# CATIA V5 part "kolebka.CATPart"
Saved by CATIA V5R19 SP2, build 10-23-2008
Part number: kolebka
Bounding box of the stored display mesh (mm): x -580 to 1160, y -1200 to 1200, z -150 to 340
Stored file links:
  D:\Catia fórum\Modely - Otazky\Naklapeni_oprava\kolebka.CATPart
  C:\Program Files\Dassault Systemes\B19\intel_a\reffiles\standard\MetricThinPitch.txt
  C:\Program Files\Dassault Systemes\B19\intel_a\startup\materials\Catalog.CATMaterial
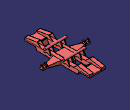
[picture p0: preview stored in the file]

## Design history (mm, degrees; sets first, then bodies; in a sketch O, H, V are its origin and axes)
WSupportSet1
Body1 (main body)
  Sketch1 on yz-plane, origin (0, 0, 0), H (0, 1, 0), V (0, 0, 1)
    construction line L1 (0, 482.4405) -> (0, -98.2488)
    point P1 (0, 482.4405)
    line L2 (0, 0) -> (-763.603, 0)
    point P3 (-763.603, 0)
    line L3 (-763.603, 0) -> (-800, 100)
    point P4 (-800, 100)
    line L4 (-800, 100) -> (-1200, 100)
    point P5 (-1200, 100)
    line L5 (-1200, 100) -> (-1200, 150)
    point P6 (-1200, 150)
    line L6 (-1200, 150) -> (0, 150)
    point P7 (0, 150)
    line L7 (0, 150) -> (0, 150)
    point P8 (0, 150)
    point P9 (0, 150)
    point P10 (763.603, 0)
    point P11 (800, 100)
    point P12 (1200, 100)
    point P13 (1200, 150)
    point P14 (0, 150)
    point P15 (0, 150)
    line L8 (763.603, 0) -> (800, 100)
    line L9 (800, 100) -> (1200, 100)
    line L10 (1200, 100) -> (1200, 150)
    line L11 (1200, 150) -> (0, 150)
    line L12 (0, 150) -> (0, 150)
    point P16 (0, 150)
    line L13 (0, 150) -> (0, 150)
    point P17 (0, 0)
    line L14 (0, 0) -> (763.603, 0)
    line L15 (-755.7735, 140) -> (-755.7735, 140)
    line L16 (755.7735, 140) -> (755.7735, 140)
    distance L5 L1 = 1200
    distance L4 L6 = 50
    distance L2 L4 = 100
    angle L2 L3 = 110
    distance P4 L5 = 400
    coincidence: P1 V, P9 L1, O P17, P9 P16, P7 P9
    vertical: L1 V, L5 V
    horizontal: L2 H, L4 H, L6 H
    symmetry: P3 P10 L1, P4 P11 L1, P5 P12 L1, P6 P13 L1, P7 P14 L1, P8 P15 L1, L3 L8 L1, L4 L9 L1, L5 L10 L1, L6 L11 L1, L7 L12 L1, P9 P16 L1, O P17 L1, L2 L14 L1
  Pad1: profile Sketch1, direction (1, 0, 0), length 140
  Shell1: IntOffset 10, Face face of Pad1 from Sketch1.L11, ExtOffset 0
  Sketch2 on face of Shell1, origin (0, -1190, 0), H (-1, 0, 0), V (0, 0, 1)
    line L1 (-130, 150) -> (-10, 150)
    line L2 (-10, 150) -> (-10, 140)
    line L3 (-10, 140) -> (-130, 140)
    line L4 (-130, 140) -> (-130, 150)
    reference projected line E1 (-130, 150) -> (-130, 110) from edge [face of Shell1 | face of Shell1]
    reference projected line E2 (-10, 150) -> (-190, 150) from edge [face of Pad1 from Sketch1.L6 | face of Shell1]
    reference projected line E3 (-10, 150) -> (-10, 110) from edge [face of Shell1 | face of Shell1]
    distance L3 L1 = 10
    horizontal: L1 H, L3 H
    vertical: L2 V, L4 V
    coincidence: E1 L4, L1 E2, E3 L2
  Pad2: profile Sketch2, direction (0, 1, 0), up to the existing solid (limit type 2)
  Sketch3 on end face of Pad1, origin (140, 0, 0), H (0, 1, 0), V (0, 0, 1)
    line L1 (-1200, 150) -> (-600, 150)
    point P2 (-600, 150)
    line L2 (-600, 150) -> (-753.4293, 278.7425)
    line L3 (-753.4293, 278.7425) -> (-1200, 200)
    point P4 (-1200, 200)
    line L4 (-1200, 200) -> (-1200, 150)
    reference projected line E1 (-1200, 150) -> (-1200, 100) from edge [face of Pad1 from Sketch1.L5 | end face of Pad1]
    reference projected line E2 (0, 150) -> (-1200, 150) from edge [face of Pad1 from Sketch1.L6 | end face of Pad1]
    angle L4 L3 = 100
    distance P2 L4 = 600
    angle L2 L1 = 40
    distance P4 L1 = 50
    horizontal: L1 H
    vertical: L4 V
    coincidence: E1 L4, L1 E2
  Pad3: profile Sketch3, direction (-1, 0, 0), length 10
  Sketch4 on end face of Pad3, origin (130, 0, 0), H (0, -1, 0), V (0, 0, 1)
    line L1 (753.4293, 278.7425) -> (1200, 200)
    line L2 (1200, 200) -> (1200, 150)
    reference projected line E1 (753.4293, 278.7425) -> (1200, 200) from edge [end face of Pad3 | face of Pad3 from Sketch3.L3]
    reference projected line E2 (1200, 200) -> (1200, 150) from edge [end face of Pad3 | face of Pad3]
    line L3 (1200, 150) -> (1190, 150)
    point P3 (1190, 150)
    reference projected line E3 (1200, 150) -> (600, 150) from edge [end face of Pad3 | face of Pad2]
    line L4 (743.4293, 270.3515) -> (1190, 191.609)
    line L5 (1190, 191.609) -> (1190, 150)
    point P5 (1190, 150)
    line L6 (753.4293, 278.7425) -> (743.4293, 270.3515)
    reference projected line E4 (600, 150) -> (753.4293, 278.7425) from edge [end face of Pad3 | face of Pad3 from Sketch3.L2]
    distance L4 L1 = 10
    distance L5 L2 = 10
    vertical: L2 V
    coincidence: E1 L1, E2 L2, L3 E3, P5 P3, E4 L6
    horizontal: L3 H
  Pad4: profile Sketch4, direction (-1, 0, 0), length 130
  Sketch5 on face of Pad4, origin (0, 0, 0), H (0, -1, 0), V (0, 0, 1)
    line L1 (743.4293, 270.3515) -> (1190, 191.609)
    line L2 (1190, 191.609) -> (1190, 150)
    line L3 (1190, 150) -> (600, 150)
    line L4 (600, 150) -> (743.4293, 270.3515)
    reference projected line E1 (-1200, 150) -> (1200, 150) from edge [face of Pad4 | face of Pad2]
    reference projected line E2 (753.4293, 278.7425) -> (743.4293, 270.3515) from edge [face of Pad4 | face of Pad4]
    reference projected line E3 (1190, 191.609) -> (1190, 150) from edge [face of Pad4 from Sketch4.L5 | face of Pad4]
    reference projected line E4 (743.4293, 270.3515) -> (1190, 191.609) from edge [face of Pad4 from Sketch4.L4 | end face of Pad4]
    vertical: L2 V
    horizontal: L3 H
    coincidence: L3 E1, L4 E2, L2 E3, L1 E4
  Pad5: profile Sketch5, direction (1, 0, 0), length 10
  Point1: type Between, FirstPoint vertex [face of Pad4 | face of Pad1 from Sketch1.L4 | face of Pad3], SecondPoint vertex [face of Pad1 from Sketch1.L10 | face of Pad1 from Sketch1.L9 | face of Pad3], Ratio 0.5
  Plane1: type 3Points, Element1 Point1, Element2 vertex [face of Pad1 from Sketch1.L2 | face of Pad1 from Sketch1.L14 | face of Pad3], Element3 vertex [face of Pad1 from Sketch1.L14 | face of Pad5 | face of Pad1 from Sketch1.L2]
  Mirror1: of Pad3, Pad4, Pad5, about Plane1
  Sketch6 on face of Mirror1, origin (140, 0, 0), H (0, 1, 0), V (0, 0, 1)
    line L1 (-763.603, 0) -> (-800, 100)
    line L2 (-807.5567, 150) -> (-752.9612, 0)
    reference projected line E1 (-800, 100) -> (-763.603, 0) from edge [face of Pad1 from Sketch1.L3 | end face of Pad1]
    line L3 (-763.603, 0) -> (-752.9612, 0)
    reference projected line E2 (-763.603, 0) -> (0, 0) from edge [face of Pad1 from Sketch1.L2 | end face of Pad1]
    line L4 (-837.5567, 150) -> (-1200, 150)
    line L5 (-1200, 150) -> (-1200, 100)
    line L6 (-1200, 100) -> (-800, 100)
    reference projected line E3 (-1200, 150) -> (-1200, 100) from edge [face of Pad4 | face of Mirror1]
    line L7 (-807.5567, 150) -> (-807.5567, 170)
    line L8 (-807.5567, 170) -> (-837.5567, 170)
    line L9 (-837.5567, 170) -> (-837.5567, 150)
    distance L1 L2 = 10
    distance L4 L6 = 50
    distance L3 L4 = 150
    distance L8 L3 = 170
    distance L9 L7 = 30
    coincidence: L1 E1, L3 E2, L5 E3
    horizontal: L4 H, L6 H, L8 H
    vertical: L5 V, L7 V, L9 V
  Pad6: profile Sketch6, direction (1, 0, 0), length 150
  Mirror2: of the body so far, about Plane1
  Plane2: type Offset, RefPlane end face of Pad6, Offset 0, reversed
  Mirror3: of the body so far, about Plane2
  Sketch7 on face of Mirror2, origin (0, 0, 0), H (0, -1, 0), V (0, 0, 1)
    point P1 (-350, 400)
    line L1 (-389.5447, 293.982) -> (-480, 100)
    point P2 (-480, 100)
    line L2 (-480, 100) -> (-420.3982, 100)
    point P3 (-220, 100)
    line L3 (-220, 100) -> (-310.4553, 293.982)
    construction line L4 (-350, 454.1532) -> (-350, 189.8921)
    point P6 (-350, 300)
    reference projected line E1 (0, 0) -> (-763.603, 0) from edge [face of Mirror2 | face of Pad1]
    arc A1 centre (-350, 300) radius 40 from (-389.5447, 293.982) to (-310.4553, 293.982) ccw
    point P9 (-355.3633, 339.6388)
    arc A2 centre (-350, 52.365) radius 85 from (-279.6018, 100) to (-420.3982, 100) ccw
    point P10 (-350, 52.365)
    line L5 (-279.6018, 100) -> (-220, 100)
    distance P6 P1 = 100
    angle L3 L2 = 65
    angle L1 L2 = 65
    distance L2 P6 = 200
    length L4 = 264.2612
    distance P3 L4 = 130
    distance P2 L4 = 130
    distance P6 V = 350
    distance L2 E1 = 100
    radius A1 = 40
    radius A2 = 85
    horizontal: L2 H, L5 H
    vertical: L4 V
    coincidence: P1 L4, P6 L4, A1 P9, P10 L4, L2 L5
  Pad7: profile Sketch7, direction (-1, 0, 0), length 15
  Pad8: profile start face of Pad7, direction along start face of Pad7, length 15
  Plane3: type Offset, RefPlane face of Mirror2, Offset 70
  Mirror4: of Pad7, Pad8, about Plane3
  Mirror5: of the body so far, about Plane2
  Mirror6: of the body so far, about Plane1
  Plane4: type Offset, RefPlane end face of Pad7, Offset 90, reversed
  Sketch8 on Plane4, origin (-105, 0, 0), H (0, 1, 0), V (0, 0, 1)
    circle A1 centre (350, 300) radius 40
    reference projected arc E1 centre (350, 300) radius 40 from (310.4553, 293.982) to (389.5447, 293.982) ccw from edge [face of Pad8 | end face of Pad7]
    radius A1 = 40
    concentricity: E1 A1
  Pad9: profile Sketch8, direction (1, 0, 0), length 790
  Mirror7: of Pad9, about Plane1
  Plane5: type Offset, RefPlane face of Mirror6, Offset 400, reversed
  Sketch9 on Plane5, origin (-400, 0, 0), H (0, 1, 0), V (0, 0, 1)
    line L1 (60, 110) -> (-60, 110)
    line L2 (-60, 110) -> (-60, 60)
    line L3 (-60, 60) -> (60, 60)
    line L4 (60, 60) -> (60, 110)
    reference projected line E1 (0, 0) -> (-763.603, 0) from edge [face of Mirror6 | face of Mirror6]
    distance V L4 = 60
    distance L2 L4 = 120
    distance L3 L1 = 50
    distance L3 E1 = 60
    horizontal: L1 H, L3 H
    vertical: L2 V, L4 V
  Sketch10 on face of Mirror6, origin (0, 0, 0), H (0, -1, 0), V (0, 0, 1)
    line L1 (-150, 150) -> (150, 150)
    line L2 (150, 150) -> (150, 0)
    line L3 (150, 0) -> (-150, 0)
    line L4 (-150, 0) -> (-150, 150)
    reference projected line E1 (-600, 150) -> (600, 150) from edge [face of Mirror6 | face of Mirror6]
    reference projected line E2 (0, 0) -> (763.603, 0) from edge [face of Mirror6 | face of Mirror6]
    distance V L2 = 150
    distance L4 L2 = 300
    horizontal: L1 H, L3 H
    vertical: L2 V, L4 V
    coincidence: L1 E1, L3 E2
  Line1: type PtPt, FirstPoint vertex [element of Sketch10 | element of Sketch10], SecondPoint vertex [element of Sketch9 | element of Sketch9]
  Line2: type PtPt, FirstPoint vertex [element of Sketch10 | element of Sketch10], SecondPoint vertex [element of Sketch9 | element of Sketch9]
  Line3: type PtPt, FirstPoint vertex [element of Sketch10 | element of Sketch10], SecondPoint vertex [element of Sketch9 | element of Sketch9]
  Line4: type PtPt, FirstPoint vertex [element of Sketch10 | element of Sketch10], SecondPoint vertex [element of Sketch9 | element of Sketch9]
  Loft1: Sections (Sketch9; Sketch10), Guides (Line4; Line1; Line2; Line3)
  ThickSurface1: Surface Loft1, TopOffset 10, BotOffset 0
  Pad10: profile Sketch9, direction (1, 0, 0), length 10
  Pad11: profile Sketch9, direction (-1, 0, 0), length 180
  Sketch11 on end face of Pad11, origin (-580, 0, 0), H (0, -1, 0), V (0, 0, 1)
    line L1 (-60, 110) -> (-60, 160)
    line L2 (-60, 160) -> (-10, 160)
    line L3 (-10, 160) -> (-10, 190)
    line L4 (-10, 190) -> (40, 190)
    line L5 (40, 190) -> (40, 110)
    line L6 (40, 110) -> (-60, 110)
    reference projected line E1 (-60, 110) -> (60, 110) from edge [end face of Pad11 | face of Pad11 from Sketch9.L1]
    reference projected line E2 (-60, 60) -> (-60, 110) from edge [end face of Pad11 | face of Pad11 from Sketch9.L4]
    distance L4 L6 = 80
    distance L3 L5 = 50
    distance L1 L5 = 100
    distance L2 L6 = 50
    vertical: L1 V, L3 V, L5 V
    horizontal: L2 H, L4 H, L6 H
    coincidence: L6 E1, L1 E2
  Pad12: profile Sketch11, direction (1, 0, 0), length 40
  Sketch12 on face of Pad12, origin (-550.9714, 60, 134.6635), H (1, 0, 0), V (0, 0, -1)
    point P1 (-9.0286, -0.3365)
    reference projected line E1 (-29.0286, 74.6635) -> (-29.0286, 24.6635) from edge [face of Pad12 | face of Pad12]
    reference projected line E2 (-19.0286, -25.3365) -> (20.9714, -25.3365) from edge [face of Pad12 from Sketch11.L2 | face of Pad12]
    distance P1 E1 = 20
    distance P1 E2 = 25
  Hole1: placed by Sketch12, at (-560, 60, 135) direction (0, -1, 0), diameter 21, depth 40
  Sketch13 on face of Pad12 from Sketch11.L5, origin (-556.5787, -40, 161.0038), H (1, 0, 0), V (0, 0, 1)
    point P1 (-3.4213, 3.9962)
    reference projected line E1 (-23.4213, -51.0038) -> (-23.4213, 18.9962) from edge [face of Pad12 from Sketch11.L5 | face of Pad12]
    reference projected line E2 (-13.4213, 28.9962) -> (26.5787, 28.9962) from edge [face of Pad12 from Sketch11.L5 | face of Pad12 from Sketch11.L4]
    distance P1 E1 = 20
    distance P1 E2 = 25
  Hole2: placed by Sketch13, at (-560, -40, 165) direction (0, 1, 0), diameter 21, depth 40
  RectPattern1: of Pad12, Hole1, Hole2, direction 1 instances 2, spacing 135, along edge [face of Pad12 from Sketch11.L5 | face of Pad12 from Sketch11.L4], direction 2 instances 2, spacing 0
  Mirror8: of the body so far, about Plane2
  Sketch14 on face of Mirror8, origin (0, 0, 150), H (1, 0, 0), V (0, 1, 0)
    line L1 (120, 200) -> (460, 200)
    line L2 (460, 200) -> (460, -200)
    line L3 (460, -200) -> (120, -200)
    line L4 (120, -200) -> (120, 200)
    distance H L1 = 200
    distance L1 L3 = 400
    distance L4 V = 120
    distance L4 L2 = 340
    horizontal: L1 H, L3 H
    vertical: L2 V, L4 V
  Pad13: profile Sketch14, direction (0, 0, 1), length 10
  Pad14: profile start face of Pad13, direction along start face of Pad13, up to face of Mirror8
  Plane6: type Offset, RefPlane face of Mirror8, Offset 57.5, reversed
  Sketch15 on Plane6, origin (382.5, 0, 0), H (0, 1, 0), V (0, 0, 1)
    line L1 (300, 150) -> (200, 150)
    line L2 (200, 150) -> (200, -150)
    line L3 (200, -150) -> (300, -150)
    line L4 (300, -150) -> (300, 150)
    reference projected line E1 (456.6846, 150) -> (600, 150) from edge [face of Mirror8 | face of Mirror8]
    reference projected line E3 (200, 150) -> (200, 0) from edge [face of Mirror8 | face of Pad13]
    distance L1 L3 = 300
    distance L2 L4 = 100
    horizontal: L1 H, L3 H
    vertical: L2 V, L4 V
    coincidence: L1 E1, L2 E3
  Pad15: profile Sketch15, direction (-1, 0, 0), length 50
  Sketch16 on face of Pad15 from Sketch15.L3, origin (401.7508, 230.7369, -150), H (1, 0, 0), V (0, -1, 0)
    point P1 (-44.2508, -19.2631)
    reference projected line E1 (-69.2508, 30.7369) -> (-69.2508, -69.2631) from edge [end face of Pad15 | face of Pad15 from Sketch15.L3]
    reference projected line E2 (18.2492, 30.7369) -> (-31.7508, 30.7369) from edge [face of Pad15 from Sketch15.L2 | face of Pad15 from Sketch15.L3]
    distance P1 E1 = 25
    distance E2 P1 = 50
  Hole3: placed by Sketch16, at (357.5, 250, -150) direction (0, 0, 1), diameter 21, depth 40
  RectPattern2: of Pad15, direction 1 instances 2, spacing 500, along edge [face of Mirror8 | face of Mirror8] reversed, direction 2 instances 2, spacing 0
  RectPattern3: of Hole3, direction 1 instances 2, spacing 500, along edge [face of Mirror8 | face of Mirror8] reversed, direction 2 instances 2, spacing 0
  Mirror9: of the body so far, about Plane2
  Sketch17 on face of Mirror9, origin (197.5, 0, 0), H (0, -1, 0), V (0, 0, 1)
    line L1 (200, 150) -> (300, 50)
    point P1 (200, 150)
    line L2 (300, 50) -> (300, 150)
    line L3 (300, 150) -> (200, 150)
    reference projected line E1 (200, 150) -> (300, 150) from edge [face of Mirror9 | face of Mirror9]
    reference projected line E2 (300, 150) -> (300, -150) from edge [face of Mirror9 | face of Mirror9]
    reference projected point E3 (200, 150) from edge [face of Mirror9 | face of Mirror9]
    angle L1 L2 = 45
    horizontal: L3 H
    coincidence: L3 E1, L2 E2, P1 E3
  Pocket1: profile Sketch17, direction (1, 0, 0), up to face of RectPattern2
  Mirror10: of Pocket1, about Plane1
